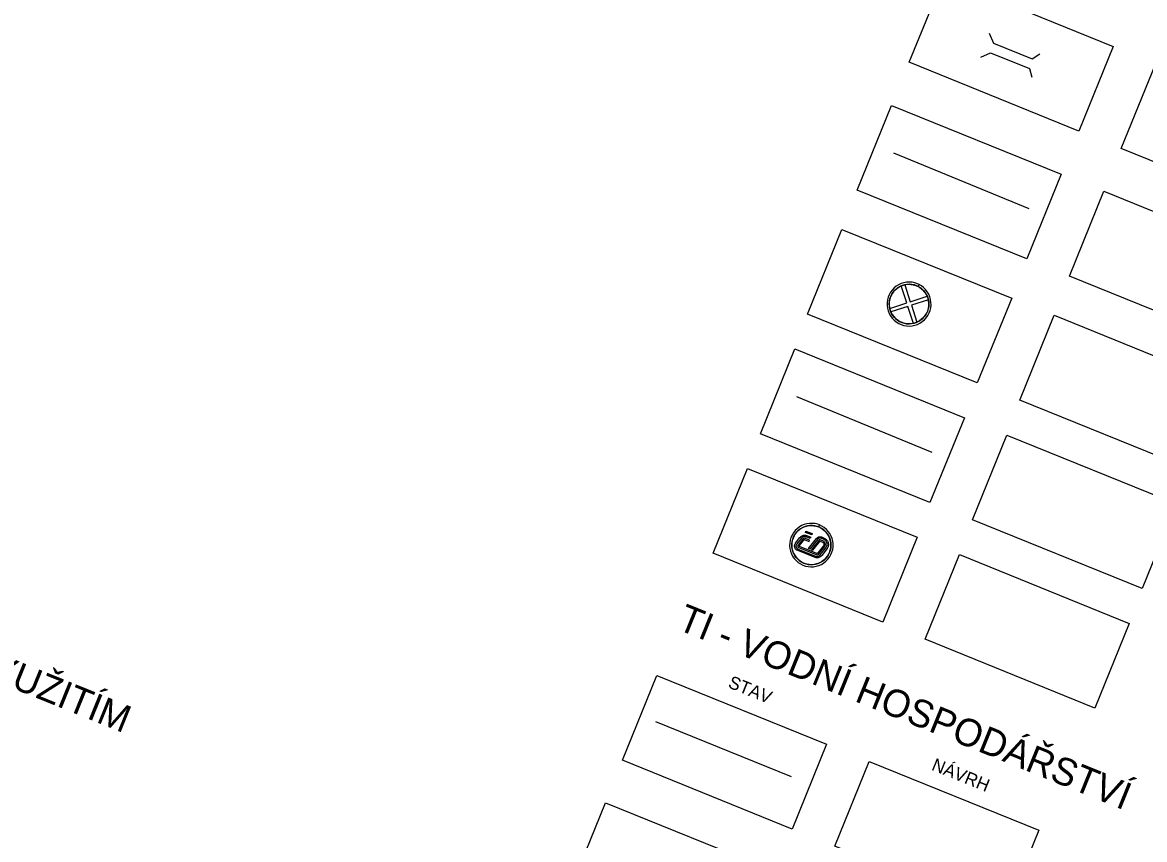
# Model space of a CAD drawing. Extents: x -522754 to -518969, y -1191121 to -1188171.
# Drawn here: x -520911 to -520298, y -1189624 to -1189177 of the extents above; entities that cross this region are included whole.
import ezdxf

# ---------------------------------------------------------------- set-up
doc = ezdxf.new("R2010")
doc.units = 0
for name, color, linetype in [('DOPRAVA', 7, 'Continuous'), ('Implicitní', 7, 'Continuous'), ('most_s', 7, 'Continuous'), ('nadrazi_s', 7, 'Continuous'), ('OP_zel_trate_s', 7, 'Continuous'), ('zel_celostat_s', 7, 'Continuous'), ('zel_prejezd_s', 7, 'Continuous')]:
    doc.layers.add(name, color=color, linetype=linetype)

msp = doc.modelspace()

# ---------------------------------------------------------------- linework, layer by layer
at = {"layer": 'Implicitní'}
msp.add_line((-520565.4, -1189559.55), (-520491.26, -1189589.6), dxfattribs=at)
for points in [[(-520407.96, -1189152.93), (-520315.31, -1189190.55), (-520334.12, -1189236.88), (-520426.77, -1189199.26)], [(-520292.14, -1189199.96), (-520199.49, -1189237.58), (-520218.3, -1189283.91), (-520310.95, -1189246.28)], [(-520436.39, -1189222.79), (-520343.72, -1189260.35), (-520362.5, -1189306.69), (-520455.17, -1189269.13)], [(-520320.55, -1189269.74), (-520227.87, -1189307.3), (-520246.65, -1189353.64), (-520339.33, -1189316.08)], [(-520463.51, -1189290.58), (-520370.82, -1189328.12), (-520389.6, -1189374.47), (-520482.28, -1189336.92)], [(-520347.65, -1189337.51), (-520254.97, -1189375.05), (-520273.74, -1189421.4), (-520366.42, -1189383.85)], [(-520489.28, -1189355.88), (-520396.63, -1189393.5), (-520415.44, -1189439.83), (-520508.09, -1189402.21)], [(-520373.47, -1189402.91), (-520280.81, -1189440.53), (-520299.62, -1189486.86), (-520392.28, -1189449.24)], [(-520515.06, -1189421.18), (-520422.4, -1189458.81), (-520441.21, -1189505.13), (-520533.87, -1189467.51)], [(-520399.24, -1189468.21), (-520306.59, -1189505.83), (-520325.4, -1189552.16), (-520418.05, -1189514.54)], [(-520564.55, -1189534.32), (-520471.88, -1189571.88), (-520490.66, -1189618.22), (-520583.33, -1189580.66)], [(-520448.71, -1189581.27), (-520356.03, -1189618.83), (-520374.81, -1189665.17), (-520467.49, -1189627.61)], [(-520592.72, -1189603.83), (-520500.05, -1189641.39), (-520518.83, -1189687.73), (-520611.5, -1189650.17)]]:
    msp.add_lwpolyline(points, close=True, dxfattribs=at)
at = {"layer": 'most_s'}
for points in [[(-520383.08, -1189183.36), (-520380.81, -1189188.72), (-520359.56, -1189197.3), (-520355.42, -1189194.7)], [(-520387.69, -1189196.36), (-520382.35, -1189194.05), (-520361.07, -1189202.56), (-520359.87, -1189207.31)]]:
    msp.add_lwpolyline(points, dxfattribs=at)
at = {"layer": 'nadrazi_s'}
for points in [[(-520475.83, -1189452.03), (-520476.76, -1189451.7), (-520478.23, -1189451.35), (-520479.72, -1189451.19), (-520481.22, -1189451.22), (-520482.71, -1189451.44), (-520484.16, -1189451.85), (-520485.54, -1189452.43), (-520486.84, -1189453.18), (-520488.04, -1189454.1), (-520489.11, -1189455.15), (-520490.04, -1189456.33), (-520490.81, -1189457.62), (-520491.41, -1189459), (-520491.84, -1189460.44), (-520492.07, -1189461.92), (-520492.12, -1189463.43), (-520491.98, -1189464.92), (-520491.66, -1189466.39), (-520491.15, -1189467.8), (-520490.46, -1189469.14), (-520489.61, -1189470.38), (-520488.62, -1189471.51), (-520487.49, -1189472.5), (-520486.24, -1189473.33), (-520484.89, -1189474.01), (-520483.48, -1189474.51), (-520482.01, -1189474.83), (-520480.51, -1189474.95), (-520479.01, -1189474.89), (-520477.53, -1189474.64), (-520476.09, -1189474.21), (-520474.72, -1189473.59), (-520473.43, -1189472.81), (-520472.26, -1189471.88), (-520471.21, -1189470.8), (-520470.31, -1189469.6), (-520469.56, -1189468.29), (-520468.99, -1189466.9), (-520468.59, -1189465.45), (-520468.39, -1189463.96), (-520468.37, -1189462.46), (-520468.54, -1189460.97), (-520468.9, -1189459.51), (-520469.44, -1189458.1), (-520470.15, -1189456.78), (-520471.03, -1189455.56), (-520472.05, -1189454.46), (-520473.2, -1189453.49), (-520474.47, -1189452.68), (-520475.82, -1189452.03)], [(-520470.31, -1189467.04), (-520469.88, -1189465.76), (-520469.63, -1189464.43), (-520469.54, -1189463.08), (-520469.63, -1189461.73), (-520469.88, -1189460.4), (-520470.3, -1189459.11), (-520470.88, -1189457.89), (-520471.61, -1189456.75), (-520472.47, -1189455.71), (-520473.46, -1189454.79), (-520474.56, -1189454), (-520475.75, -1189453.36), (-520477.01, -1189452.87), (-520478.32, -1189452.54), (-520479.67, -1189452.38), (-520481.02, -1189452.4), (-520482.36, -1189452.58), (-520483.67, -1189452.93), (-520484.92, -1189453.45), (-520486.1, -1189454.11), (-520487.18, -1189454.92), (-520488.15, -1189455.86), (-520489, -1189456.92), (-520489.7, -1189458.07), (-520490.26, -1189459.31), (-520490.65, -1189460.6), (-520490.88, -1189461.93), (-520490.94, -1189463.29), (-520490.83, -1189464.63), (-520490.54, -1189465.96), (-520490.1, -1189467.23), (-520489.49, -1189468.44), (-520488.74, -1189469.57), (-520487.85, -1189470.59), (-520486.84, -1189471.49), (-520485.73, -1189472.25), (-520484.53, -1189472.87), (-520483.25, -1189473.34), (-520481.94, -1189473.63), (-520480.59, -1189473.76), (-520479.24, -1189473.72), (-520477.9, -1189473.51), (-520476.6, -1189473.13), (-520475.36, -1189472.59), (-520474.2, -1189471.9), (-520473.13, -1189471.07), (-520472.18, -1189470.11), (-520471.36, -1189469.03), (-520470.68, -1189467.86), (-520470.31, -1189467.04)], [(-520476.26, -1189453.14), (-520475.45, -1189453.5), (-520474.28, -1189454.18), (-520473.21, -1189455.01), (-520472.25, -1189455.96), (-520471.41, -1189457.02), (-520470.72, -1189458.18), (-520470.18, -1189459.42), (-520469.8, -1189460.72), (-520469.59, -1189462.06), (-520469.55, -1189463.41), (-520469.68, -1189464.76), (-520469.97, -1189466.08), (-520470.43, -1189467.35), (-520471.05, -1189468.55), (-520471.82, -1189469.67), (-520472.72, -1189470.68), (-520473.74, -1189471.57), (-520474.86, -1189472.32), (-520476.07, -1189472.92), (-520477.35, -1189473.37), (-520478.67, -1189473.65), (-520480.02, -1189473.77), (-520481.37, -1189473.71), (-520482.7, -1189473.48), (-520484, -1189473.09), (-520485.23, -1189472.53), (-520486.39, -1189471.83), (-520487.44, -1189470.98), (-520488.38, -1189470.01), (-520489.19, -1189468.93), (-520489.86, -1189467.75), (-520490.38, -1189466.5), (-520490.73, -1189465.19), (-520490.91, -1189463.85), (-520490.93, -1189462.5), (-520490.77, -1189461.16), (-520490.44, -1189459.84), (-520489.96, -1189458.58), (-520489.31, -1189457.39), (-520488.52, -1189456.29), (-520487.6, -1189455.3), (-520486.56, -1189454.44), (-520485.42, -1189453.71), (-520484.2, -1189453.13), (-520482.92, -1189452.71), (-520481.59, -1189452.45), (-520480.24, -1189452.37), (-520478.89, -1189452.46), (-520477.56, -1189452.71), (-520476.27, -1189453.13)], [(-520476.27, -1189453.13), (-520475.83, -1189452.03)], [(-520475.82, -1189452.03), (-520476.26, -1189453.14)], [(-520486.46, -1189458.95), (-520486.2, -1189458.65), (-520485.91, -1189458.38), (-520485.59, -1189458.15), (-520485.25, -1189457.96), (-520484.9, -1189457.82), (-520484.53, -1189457.72), (-520484.15, -1189457.66), (-520483.78, -1189457.66), (-520483.41, -1189457.7), (-520483.05, -1189457.79), (-520482.88, -1189457.86)], [(-520483.16, -1189458.55), (-520483.42, -1189458.47), (-520483.69, -1189458.41), (-520483.97, -1189458.4), (-520484.25, -1189458.42), (-520484.53, -1189458.48), (-520484.8, -1189458.58), (-520485.06, -1189458.7), (-520485.31, -1189458.86), (-520485.55, -1189459.05), (-520485.76, -1189459.27), (-520485.88, -1189459.42)], [(-520480.05, -1189457.49), (-520483.5, -1189456.12), (-520483.22, -1189455.42), (-520479.77, -1189456.8), (-520480.05, -1189457.49)], [(-520480.87, -1189459.46), (-520483.16, -1189458.55)], [(-520482.88, -1189457.86), (-520480.6, -1189458.77)], [(-520482.88, -1189457.86), (-520482.88, -1189457.86)], [(-520480.6, -1189458.77), (-520480.87, -1189459.46)], [(-520477.5, -1189459.47), (-520477.3, -1189459.23), (-520477.08, -1189459.03), (-520476.84, -1189458.85), (-520476.57, -1189458.7), (-520476.3, -1189458.59), (-520476.02, -1189458.52), (-520475.73, -1189458.47), (-520475.44, -1189458.47), (-520475.16, -1189458.5), (-520474.89, -1189458.58), (-520474.75, -1189458.62)], [(-520474.75, -1189458.62), (-520473.26, -1189459.22)], [(-520487.97, -1189465.92), (-520488.22, -1189465.8), (-520488.46, -1189465.64), (-520488.68, -1189465.45), (-520488.87, -1189465.24), (-520489.04, -1189465), (-520489.17, -1189464.74), (-520489.28, -1189464.46), (-520489.35, -1189464.17), (-520489.39, -1189463.87), (-520489.39, -1189463.56), (-520489.36, -1189463.26), (-520489.29, -1189462.96), (-520489.19, -1189462.66), (-520489.06, -1189462.38), (-520488.9, -1189462.12), (-520488.82, -1189462.01)], [(-520488.82, -1189462.01), (-520486.46, -1189458.95)], [(-520488.24, -1189462.48), (-520488.36, -1189462.66), (-520488.46, -1189462.85), (-520488.54, -1189463.05), (-520488.59, -1189463.25), (-520488.63, -1189463.46), (-520488.65, -1189463.68), (-520488.64, -1189463.89), (-520488.6, -1189464.09), (-520488.55, -1189464.29), (-520488.47, -1189464.47), (-520488.38, -1189464.65), (-520488.26, -1189464.81), (-520488.13, -1189464.95), (-520487.98, -1189465.07), (-520487.82, -1189465.17), (-520487.69, -1189465.22)], [(-520485.88, -1189459.42), (-520488.22, -1189462.46)], [(-520487.51, -1189463.07), (-520487.56, -1189463.14), (-520487.6, -1189463.23), (-520487.64, -1189463.32), (-520487.67, -1189463.41), (-520487.7, -1189463.5), (-520487.71, -1189463.6), (-520487.71, -1189463.69), (-520487.71, -1189463.78), (-520487.7, -1189463.87), (-520487.68, -1189463.95), (-520487.65, -1189464.03), (-520487.62, -1189464.11), (-520487.57, -1189464.18), (-520487.52, -1189464.23), (-520487.47, -1189464.28), (-520487.41, -1189464.33), (-520487.34, -1189464.36)], [(-520485.13, -1189459.97), (-520487.51, -1189463.07)], [(-520487.34, -1189464.36), (-520477.55, -1189468.28)], [(-520486.66, -1189463.83), (-520486.68, -1189463.82), (-520486.71, -1189463.8), (-520486.74, -1189463.78), (-520486.77, -1189463.75), (-520486.8, -1189463.72), (-520486.82, -1189463.68), (-520486.83, -1189463.65), (-520486.84, -1189463.61), (-520486.85, -1189463.57), (-520486.85, -1189463.53), (-520486.85, -1189463.49), (-520486.84, -1189463.46), (-520486.83, -1189463.42), (-520486.81, -1189463.38), (-520486.79, -1189463.35)], [(-520486.79, -1189463.35), (-520484.57, -1189460.47)], [(-520477.27, -1189467.58), (-520486.66, -1189463.83)], [(-520483.51, -1189459.42), (-520483.51, -1189459.42), (-520483.66, -1189459.37), (-520483.82, -1189459.34), (-520483.98, -1189459.33), (-520484.14, -1189459.35), (-520484.3, -1189459.39), (-520484.46, -1189459.44), (-520484.62, -1189459.52), (-520484.77, -1189459.62), (-520484.91, -1189459.73), (-520485.04, -1189459.86), (-520485.13, -1189459.97)], [(-520484.57, -1189460.48), (-520484.57, -1189460.47), (-520484.51, -1189460.4), (-520484.46, -1189460.33), (-520484.39, -1189460.27), (-520484.33, -1189460.22), (-520484.26, -1189460.17), (-520484.19, -1189460.13), (-520484.12, -1189460.11), (-520484.05, -1189460.09), (-520483.98, -1189460.08), (-520483.91, -1189460.08), (-520483.85, -1189460.09), (-520483.8, -1189460.11)], [(-520483.8, -1189460.11), (-520481.5, -1189461.02)], [(-520481.22, -1189460.33), (-520483.51, -1189459.41)], [(-520481.76, -1189465), (-520477.5, -1189459.47)], [(-520481.04, -1189465.29), (-520481.76, -1189465)], [(-520481.5, -1189461.02), (-520481.22, -1189460.33)], [(-520476.92, -1189459.93), (-520481.04, -1189465.29)], [(-520476.2, -1189460.52), (-520480.14, -1189465.64)], [(-520479.42, -1189465.93), (-520475.7, -1189461.1)], [(-520475.03, -1189459.32), (-520475.21, -1189459.26), (-520475.4, -1189459.22), (-520475.59, -1189459.22), (-520475.78, -1189459.23), (-520475.98, -1189459.27), (-520476.17, -1189459.34), (-520476.35, -1189459.43), (-520476.52, -1189459.54), (-520476.68, -1189459.67), (-520476.83, -1189459.82), (-520476.92, -1189459.93)], [(-520473.61, -1189463.48), (-520476.45, -1189467.16)], [(-520475.38, -1189460.18), (-520475.41, -1189460.17), (-520475.49, -1189460.15), (-520475.56, -1189460.15), (-520475.64, -1189460.15), (-520475.71, -1189460.16), (-520475.79, -1189460.19), (-520475.87, -1189460.22), (-520475.94, -1189460.27), (-520476.01, -1189460.32), (-520476.08, -1189460.38), (-520476.14, -1189460.45), (-520476.2, -1189460.52)], [(-520475.91, -1189467.69), (-520473.02, -1189463.94)], [(-520475.7, -1189461.1), (-520475.7, -1189461.09), (-520475.67, -1189461.06), (-520475.64, -1189461.04), (-520475.61, -1189461.02), (-520475.57, -1189461), (-520475.53, -1189460.99), (-520475.5, -1189460.98), (-520475.46, -1189460.98), (-520475.42, -1189460.98), (-520475.38, -1189460.99), (-520475.34, -1189461)], [(-520473.88, -1189460.78), (-520475.38, -1189460.18)], [(-520475.34, -1189461), (-520474.16, -1189461.47)], [(-520475.19, -1189468.28), (-520472.28, -1189464.51)], [(-520473.54, -1189459.91), (-520475.03, -1189459.32)], [(-520471.69, -1189464.97), (-520474.6, -1189468.74)], [(-520474.16, -1189461.47), (-520474.07, -1189461.51), (-520473.93, -1189461.6), (-520473.8, -1189461.7), (-520473.68, -1189461.81), (-520473.57, -1189461.94), (-520473.49, -1189462.08), (-520473.42, -1189462.23), (-520473.37, -1189462.39), (-520473.35, -1189462.55), (-520473.34, -1189462.72), (-520473.35, -1189462.88), (-520473.39, -1189463.04), (-520473.44, -1189463.2), (-520473.52, -1189463.35), (-520473.61, -1189463.48)], [(-520473.02, -1189463.94), (-520472.93, -1189463.81), (-520472.8, -1189463.59), (-520472.7, -1189463.35), (-520472.63, -1189463.1), (-520472.6, -1189462.84), (-520472.6, -1189462.58), (-520472.63, -1189462.32), (-520472.69, -1189462.07), (-520472.78, -1189461.83), (-520472.9, -1189461.6), (-520473.05, -1189461.39), (-520473.23, -1189461.2), (-520473.43, -1189461.03), (-520473.65, -1189460.89), (-520473.88, -1189460.78)], [(-520472.28, -1189464.51), (-520472.07, -1189464.2), (-520471.9, -1189463.86), (-520471.77, -1189463.5), (-520471.69, -1189463.13), (-520471.66, -1189462.76), (-520471.67, -1189462.38), (-520471.74, -1189462.01), (-520471.85, -1189461.65), (-520472, -1189461.3), (-520472.2, -1189460.98), (-520472.43, -1189460.68), (-520472.7, -1189460.42), (-520473, -1189460.19), (-520473.33, -1189460.01), (-520473.54, -1189459.91)], [(-520473.26, -1189459.22), (-520472.83, -1189459.42), (-520472.44, -1189459.68), (-520472.07, -1189459.98), (-520471.75, -1189460.33), (-520471.48, -1189460.71), (-520471.25, -1189461.13), (-520471.08, -1189461.57), (-520470.97, -1189462.02), (-520470.92, -1189462.49), (-520470.92, -1189462.97), (-520470.99, -1189463.43), (-520471.11, -1189463.89), (-520471.29, -1189464.32), (-520471.52, -1189464.73), (-520471.69, -1189464.96)], [(-520478.17, -1189469.84), (-520487.96, -1189465.92)], [(-520487.69, -1189465.23), (-520477.9, -1189469.14)], [(-520480.14, -1189465.64), (-520479.42, -1189465.93)], [(-520474.6, -1189468.74), (-520474.86, -1189469.04), (-520475.15, -1189469.31), (-520475.47, -1189469.54), (-520475.81, -1189469.73), (-520476.16, -1189469.87), (-520476.53, -1189469.97), (-520476.9, -1189470.03), (-520477.28, -1189470.03), (-520477.64, -1189469.99), (-520478, -1189469.9), (-520478.17, -1189469.83)], [(-520477.9, -1189469.14), (-520477.64, -1189469.23), (-520477.36, -1189469.28), (-520477.09, -1189469.29), (-520476.81, -1189469.27), (-520476.53, -1189469.21), (-520476.26, -1189469.11), (-520475.99, -1189468.99), (-520475.74, -1189468.83), (-520475.51, -1189468.64), (-520475.3, -1189468.42), (-520475.18, -1189468.27)], [(-520477.55, -1189468.27), (-520477.55, -1189468.28), (-520477.4, -1189468.32), (-520477.24, -1189468.35), (-520477.08, -1189468.36), (-520476.92, -1189468.34), (-520476.76, -1189468.3), (-520476.6, -1189468.25), (-520476.44, -1189468.17), (-520476.29, -1189468.07), (-520476.15, -1189467.96), (-520476.02, -1189467.83), (-520475.91, -1189467.69)], [(-520476.45, -1189467.16), (-520476.54, -1189467.29), (-520476.6, -1189467.36), (-520476.66, -1189467.42), (-520476.73, -1189467.47), (-520476.8, -1189467.52), (-520476.87, -1189467.56), (-520476.94, -1189467.58), (-520477.01, -1189467.6), (-520477.08, -1189467.61), (-520477.15, -1189467.61), (-520477.21, -1189467.6), (-520477.27, -1189467.58)]]:
    msp.add_lwpolyline(points, dxfattribs=at)
at = {"layer": 'OP_zel_trate_s'}
msp.add_line((-520488.37, -1189381.89), (-520414.41, -1189412.36), dxfattribs=at)
at = {"layer": 'zel_celostat_s'}
msp.add_line((-520435.43, -1189248.74), (-520361.46, -1189279.22), dxfattribs=at)
at = {"layer": 'zel_prejezd_s'}
for points in [[(-520421.43, -1189320.65), (-520422.34, -1189320.23), (-520423.78, -1189319.75), (-520425.26, -1189319.45), (-520426.78, -1189319.35), (-520428.29, -1189319.43), (-520429.79, -1189319.71), (-520431.23, -1189320.17), (-520432.61, -1189320.81), (-520433.89, -1189321.62), (-520435.07, -1189322.58), (-520436.11, -1189323.69), (-520437, -1189324.91), (-520437.73, -1189326.24), (-520438.29, -1189327.66), (-520438.67, -1189329.13), (-520438.85, -1189330.63), (-520438.85, -1189332.15), (-520438.65, -1189333.66), (-520438.27, -1189335.13), (-520437.7, -1189336.53), (-520436.96, -1189337.86), (-520436.06, -1189339.08), (-520435.01, -1189340.18), (-520433.83, -1189341.14), (-520432.54, -1189341.94), (-520431.16, -1189342.57), (-520429.71, -1189343.02), (-520428.22, -1189343.29), (-520426.7, -1189343.36), (-520425.19, -1189343.24), (-520423.7, -1189342.94), (-520422.27, -1189342.45), (-520420.9, -1189341.78), (-520419.64, -1189340.94), (-520418.48, -1189339.95), (-520417.47, -1189338.83), (-520416.6, -1189337.58), (-520415.9, -1189336.23), (-520415.37, -1189334.81), (-520415.02, -1189333.33), (-520414.87, -1189331.82), (-520414.91, -1189330.3), (-520415.13, -1189328.8), (-520415.55, -1189327.34), (-520416.15, -1189325.95), (-520416.92, -1189324.64), (-520417.84, -1189323.44), (-520418.91, -1189322.36), (-520420.11, -1189321.43), (-520421.42, -1189320.65)], [(-520421.96, -1189321.72), (-520421.18, -1189322.17), (-520420.07, -1189322.96), (-520419.06, -1189323.88), (-520418.18, -1189324.93), (-520417.44, -1189326.07), (-520416.85, -1189327.31), (-520416.42, -1189328.6), (-520416.15, -1189329.94), (-520416.06, -1189331.31), (-520416.14, -1189332.67), (-520416.39, -1189334.01), (-520416.81, -1189335.31), (-520417.39, -1189336.55), (-520418.12, -1189337.71), (-520418.99, -1189338.76), (-520419.99, -1189339.69), (-520421.1, -1189340.49), (-520422.3, -1189341.15), (-520423.57, -1189341.65), (-520424.9, -1189341.98), (-520426.25, -1189342.14), (-520427.62, -1189342.14), (-520428.97, -1189341.96), (-520430.29, -1189341.61), (-520431.56, -1189341.09), (-520432.75, -1189340.42), (-520433.85, -1189339.61), (-520434.83, -1189338.66), (-520435.69, -1189337.6), (-520436.41, -1189336.43), (-520436.97, -1189335.19), (-520437.38, -1189333.88), (-520437.61, -1189332.54), (-520437.67, -1189331.17), (-520437.57, -1189329.81), (-520437.29, -1189328.47), (-520436.84, -1189327.18), (-520436.23, -1189325.96), (-520435.48, -1189324.82), (-520434.58, -1189323.79), (-520433.57, -1189322.87), (-520432.44, -1189322.1), (-520431.23, -1189321.47), (-520429.95, -1189321), (-520428.62, -1189320.69), (-520427.26, -1189320.55), (-520425.89, -1189320.59), (-520424.54, -1189320.8), (-520423.23, -1189321.18), (-520421.97, -1189321.72)], [(-520417.24, -1189336.26), (-520416.69, -1189335), (-520416.31, -1189333.69), (-520416.1, -1189332.34), (-520416.07, -1189330.97), (-520416.2, -1189329.61), (-520416.51, -1189328.28), (-520416.98, -1189327), (-520417.61, -1189325.78), (-520418.38, -1189324.66), (-520419.3, -1189323.64), (-520420.33, -1189322.75), (-520421.47, -1189321.99), (-520422.69, -1189321.39), (-520423.98, -1189320.94), (-520425.32, -1189320.66), (-520426.68, -1189320.55), (-520428.05, -1189320.61), (-520429.39, -1189320.85), (-520430.7, -1189321.25), (-520431.94, -1189321.81), (-520433.11, -1189322.53), (-520434.17, -1189323.39), (-520435.12, -1189324.37), (-520435.93, -1189325.47), (-520436.6, -1189326.66), (-520437.12, -1189327.93), (-520437.47, -1189329.25), (-520437.65, -1189330.6), (-520437.66, -1189331.97), (-520437.49, -1189333.32), (-520437.16, -1189334.65), (-520436.66, -1189335.92), (-520436.01, -1189337.12), (-520435.21, -1189338.23), (-520434.28, -1189339.23), (-520433.22, -1189340.1), (-520432.07, -1189340.83), (-520430.83, -1189341.41), (-520429.53, -1189341.83), (-520428.19, -1189342.08), (-520426.83, -1189342.16), (-520425.46, -1189342.07), (-520424.12, -1189341.81), (-520422.82, -1189341.38), (-520421.59, -1189340.79), (-520420.44, -1189340.05), (-520419.4, -1189339.17), (-520418.47, -1189338.16), (-520417.68, -1189337.05), (-520417.24, -1189336.26)], [(-520428.14, -1189330.71), (-520431.16, -1189321.43), (-520429.26, -1189320.81)], [(-520428.13, -1189330.71), (-520431.15, -1189321.43), (-520429.25, -1189320.81)], [(-520429.26, -1189320.81), (-520426.24, -1189330.09)], [(-520429.25, -1189320.81), (-520426.23, -1189330.09)], [(-520421.97, -1189321.72), (-520421.43, -1189320.65)], [(-520421.42, -1189320.65), (-520421.96, -1189321.72)], [(-520426.24, -1189330.09), (-520416.95, -1189327.07), (-520416.33, -1189328.97)], [(-520426.23, -1189330.09), (-520416.95, -1189327.07), (-520416.33, -1189328.98)], [(-520416.33, -1189328.97), (-520425.62, -1189331.99)], [(-520416.33, -1189328.98), (-520425.61, -1189332)], [(-520437.42, -1189333.73), (-520428.14, -1189330.71)], [(-520427.52, -1189332.61), (-520436.8, -1189335.63), (-520437.42, -1189333.73)], [(-520437.41, -1189333.74), (-520428.13, -1189330.71)], [(-520427.51, -1189332.62), (-520436.79, -1189335.64), (-520437.41, -1189333.74)], [(-520424.5, -1189341.89), (-520427.52, -1189332.61)], [(-520424.49, -1189341.9), (-520427.51, -1189332.62)], [(-520425.62, -1189331.99), (-520422.59, -1189341.27), (-520424.5, -1189341.89)], [(-520425.61, -1189332), (-520422.58, -1189341.28), (-520424.49, -1189341.9)]]:
    msp.add_lwpolyline(points, dxfattribs=at)

# ---------------------------------------------------------------- texts
at = {"layer": 'DOPRAVA'}
msp.add_text('PLOCHA PŘI OKRAJI LESA S PODM. VYUŽITÍM', height=15, rotation=337.93806, dxfattribs=at).set_placement((-521269.12, -1189398.42))
at = {"layer": 'Implicitní'}
for s, height, p in [('TI - VODNÍ HOSPODÁŘSTVÍ', 15, (-520554.22, -1189508.83)), ('STAV', 7, (-520526.19, -1189540.7)), ('NÁVRH', 7, (-520415.04, -1189585.74))]:
    msp.add_text(s, height=height, rotation=337.93793, dxfattribs=at).set_placement(p)

doc.saveas('drawing.dxf')
